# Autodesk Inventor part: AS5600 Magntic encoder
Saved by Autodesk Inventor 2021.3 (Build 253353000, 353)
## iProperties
Created: 2022-03
Part Number: AS5600 Magntic encoder
Material: Generic
Document SubType Name: Modeling
Designer: Administrator
Density: 1 g/cm^3
Appearance: Default
Title: AS5600 Magntic encoder v1
Author: Administrator
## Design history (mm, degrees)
feature "Body1"
body "Solid1"
